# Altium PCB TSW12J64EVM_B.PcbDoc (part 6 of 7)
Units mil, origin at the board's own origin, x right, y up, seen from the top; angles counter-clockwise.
Board outline 8833 x 2680 mil, 10 copper layers (Top Layer L1, Gnd-Plane - L2, Signals - L3, Gnd-Plane - L4, Pwr Plane - L5, Signals - L6, Gnd-Plane - L7, Signals - L8, Gnd-Plane - L9, Bottom Layer - L10), stack 57.8 mil thick; 950 components, 533 nets, 2888 pads, 1732 vias.
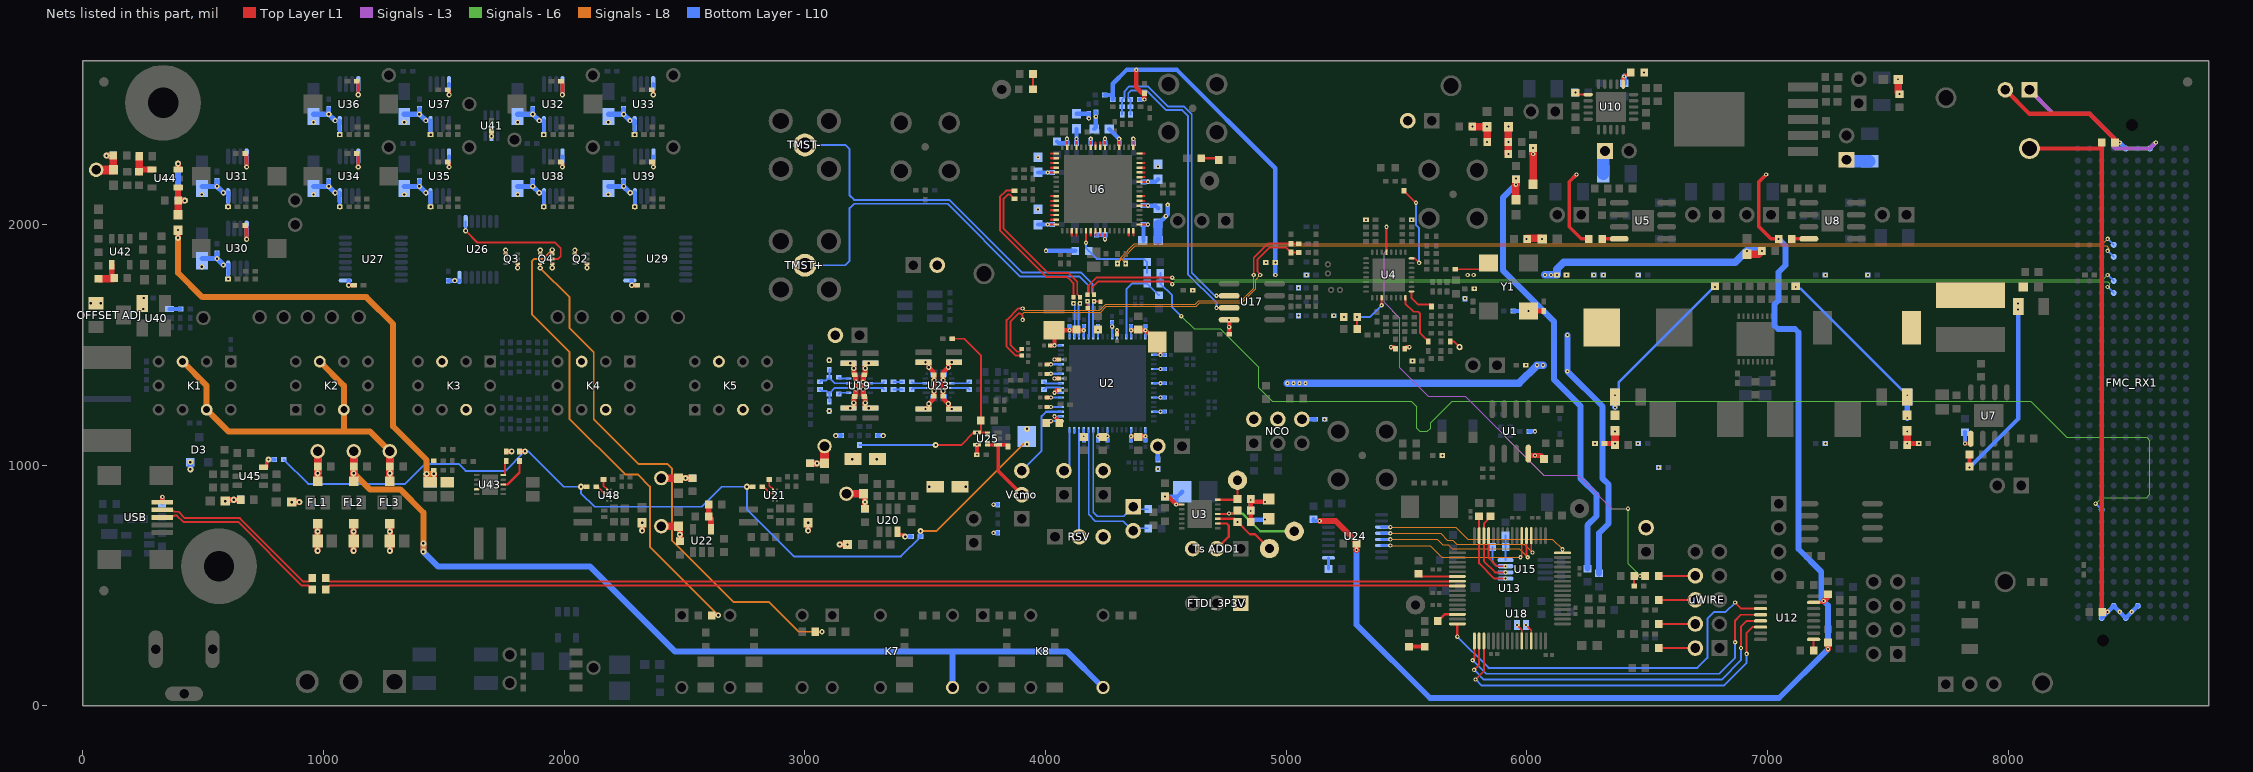
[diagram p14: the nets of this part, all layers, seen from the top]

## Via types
v1: diameter 18, hole 8, Top Layer L1 to Bottom Layer - L10, tented both sides, 1096 vias
v2: diameter 21.46, hole 10, Top Layer L1 to Bottom Layer - L10, tented both sides, 266 vias
v3: diameter 25, hole 10, Top Layer L1 to Bottom Layer - L10, tented both sides, 154 vias
v4: diameter 19.68, hole 7.87, Top Layer L1 to Bottom Layer - L10, 103 vias
v5: diameter 18, hole 8, Top Layer L1 to Bottom Layer - L10, tented bottom, 42 vias
v6: diameter 18, hole 8, Top Layer L1 to Bottom Layer - L10, tented top, 24 vias
v7: diameter 18, hole 8.01, Top Layer L1 to Bottom Layer - L10, tented both sides, 16 vias
v8: diameter 18, hole 8.01, Top Layer L1 to Bottom Layer - L10, tented bottom, 16 vias
v9: diameter 25.98, hole 12.99, Top Layer L1 to Bottom Layer - L10, tented top, 8 vias
v10: diameter 19.68, hole 7.87, Top Layer L1 to Bottom Layer - L10, tented top, 5 vias
v11: diameter 126, hole 106, Top Layer L1 to Bottom Layer - L10, tented top, 2 vias

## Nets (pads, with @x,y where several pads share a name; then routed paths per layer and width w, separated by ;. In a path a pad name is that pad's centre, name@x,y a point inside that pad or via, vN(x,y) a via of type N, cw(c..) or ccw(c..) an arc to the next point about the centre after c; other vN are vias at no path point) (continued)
NetQ4_3: Q4.3 R264.1 | length 2253.9
  Top Layer L1 w8: v2(1901,1818.65) Q4.3@1901,1836.39 ; R264.1@3044.12,307.56 v2(3071.6,307.56)
  Signals - L8 w8: v2(1901,1818.65) 2023,1696.65 2023,1569 2123,1469 2123,1191 2309,1005 2428,1005 2449,984 2449,686 2703,432 2850,432 2974.44,307.56 v2(3071.6,307.56)
NetQ4_5: Q4.5 U26.2 | length 537.6
  Top Layer L1 w8: v2(1590.82,1973.85) 1640.17,1924.5 1963.27,1924.5 1986,1901.77 1986,1866.77 1975.61,1856.39 Q4.5@1951,1856.39
  Bottom Layer - L10 w8: v2(1590.82,1973.85) U26.2@1590.82,2012.14
NetQ4_6: Q4.6 R263.1 | length 1971.8
  Top Layer L1 w8: Q4.6@1951,1876.39 v2(1951,1894.12) ; R263.1@2612.56,376 v2(2640.04,376)
  Signals - L8 w8: v2(1951,1894.12) 1913.27,1856.39 1876.39,1856.39 1866,1846 1866,1626 2023,1469 2023,1191 2253,961 2306,961 2356,911 2356,660.04 v2(2640.04,376)
NetR13_1: R13.1 U2.2 | length 62.9
  Top Layer L1 w18: v1(4037.26,1202.2) 4057.82,1181.65 R13.1@4057.82,1175
  Bottom Layer - L10 w9: v1(4037.26,1202.2) U2.2@4064.47,1202.2
NetR13_2: R13.2 U2.1 | length 64.9
  Top Layer L1 w18: R13.2@4002.7,1175 4010.22,1182.52 v1(4022.26,1182.52)
  Bottom Layer - L10 w9: v1(4022.26,1182.52) U2.1@4064.47,1182.52
NetR17_2: R17.2 TEMP.2 | length 63.6
  Bottom Layer - L10 w18: R17.2@4852.84,763.41 4862.84,773.41 v1(4912.28,773.41)
NetR26_2: R26.2 R133.1 Y1.1 | length 127.6
  Top Layer L1 w19.68: v1(6005.91,1640) R26.2@6070.47,1640
  Bottom Layer - L10 w18: R133.1@5942.92,1640 v1(6005.91,1640)
NetR38_2: R38.2 Y1.3 | length 149.8
  Top Layer L1 w8: R38.2@5701.69,1813.68 5814.24,1813.68 Y1.3@5840.56,1840
NetR39_2: R39.2 U5.8 | length 71
  Top Layer L1 w15: R39.2@6312.56,1940 U5.8@6383.57,1940
NetR45_2: R45.2 Status2.2 | length 63.7
  Top Layer L1 w9: Status2.2@3948.05,2561.29 R45.2@3948.06,2625
NetR47_1: R47.1 R142.2 R143.2 U6.6 | length 395.4
  Top Layer L1 w9: v1(4168.35,1923.69) U6.6@4168.35,1973.77
  Bottom Layer - L10 w8: v1(4168.35,1923.69) 4168.35,1901 R47.1@4179.35,1890 4212.35,1857 4408.44,1857 R142.2@4422.44,1843 R143.2@4422.44,1798.5
NetR52_1: R52.1 USB.2 | length 753.7
  Top Layer L1 w8: USB.2@330.71,813.93 371.71,813.93 379.46,806.18 397.98,806.18 424.17,780 652.63,780 916.94,515.69 938.24,515.69 R52.1@954.24,531.69
NetR52_2: R52.2 U13.7 | length 4709
  Top Layer L1 w8: R52.2@1009.36,531.69 1025.36,515.69 5676.63,515.69 5678.47,517.53 U13.7@5710.97,517.53
NetR53_1: R53.1 USB.3 | length 753.7
  Top Layer L1 w8: USB.3@330.71,782.44 371.71,782.44 379.46,790.18 391.36,790.18 417.54,764 646,764 910.31,499.69 938.24,499.69 R53.1@954.24,483.69
NetR53_2: R53.2 U13.8 | length 4709
  Top Layer L1 w8: R53.2@1009.36,483.69 1025.36,499.69 5676.63,499.69 5678.47,497.84 U13.8@5710.97,497.84
NetR56_2: R56.2 Status1.2 | length 72.9
  Top Layer L1 w9: Status1.2@4647.03,2274.95 R56.2@4719.94,2274.95
NetR65_2: R65.2 U12.9 | length 47
  Top Layer L1 w8: R65.2@7191.24,229 U12.9@7191.24,275.96
NetR66_1: R66.1 U13.14 | length 92.5
  Top Layer L1 w10: R66.1@5630.03,351.73 5658.03,379.73 U13.14@5710.97,379.73
NetR67_2: R67.2 U13.6 | length 164.9
  Top Layer L1 w10: R67.2@5550.47,547.96 5561.22,537.21 U13.6@5710.97,537.21
NetR70_2: R70.2 U7.1 | length 71.1
  Top Layer L1 w18: v1(7820.19,1090) U7.1@7844,1090
  Bottom Layer - L10 w18: v1(7820.19,1090) R70.2@7820.19,1137.29
NetR71_2: R71.2 U8.8 | length 71
  Top Layer L1 w15: R71.2@7100.56,1940 U8.8@7171.57,1940
NetR80_2: R80.2 R89.2 U10.11 | length 96
  Top Layer L1 w13.5: U10.11@6399.86,2582.49 6399.86,2609.67 v1(6404.36,2614.17) 6411.18,2621 6422.1,2621 R80.2@6432.1,2631
  Bottom Layer - L10 w24: R89.2@6404.36,2586.43 v1(6404.36,2614.17)
NetR85_1: R85.1 R88.2 U10.16 | length 55
  Top Layer L1 w8: v1(6202.68,2547.56) 6211.05,2539.18 U10.16@6254.19,2539.18
NetR97_2: R97.2 uWIRE.8 | length 152.4
  Top Layer L1 w8: R97.2@6547.56,540 uWIRE.8@6700,540
NetR98_2: R98.2 uWIRE.6 | length 152.4
  Top Layer L1 w8: R98.2@6547.56,440 uWIRE.6@6700,440
NetR99_1: R99.1 Tdiode.2 U2.64 | length 632.6
  Bottom Layer - L10 w6: U2.64@4178.65,1147.09 4178.65,796.36 4207.35,767.66 4323.62,767.66 Tdiode.2@4364.28,727 ; Tdiode.2@4364,727.28 4373.72,737 R99.1@4427.44,737
NetR100_1: R100.1 Tdiode.1 U2.63 | length 599.4
  Bottom Layer - L10 w6: U2.63@4198.33,1147.09 4198.33,804.52 4215.5,787.34 4324.62,787.34 Tdiode.1@4364.28,827 4374.28,817 R100.1@4427.44,817
NetR101_2: R101.2 uWIRE.4 | length 152.4
  Top Layer L1 w8: R101.2@6547.56,340 uWIRE.4@6700,340
NetR102_2: R102.2 uWIRE.2 | length 152.4
  Top Layer L1 w8: R102.2@6547.56,240 uWIRE.2@6700,240
NetR103_1: R103.1 USB.1 | length 49.6
  Top Layer L1 w19.5: USB.1@330.71,845.43 v1(330.71,867.27)
  Bottom Layer - L10 w16.5: R103.1@330.71,839.52 v1(330.71,867.27)
NetR105_1: R105.1 R108.2 U15.4 | length 102.1
  Bottom Layer - L10 w8: U15.4@5911.32,605.39 R108.2@5911.32,659 R105.1@5911.32,707.44
NetR106_1: R106.1 U13.62 U15.2 | length 307.2
  Top Layer L1 w8: R106.1@5848.2,787.44 5848.2,783.44 5821.2,756.44 U13.62@5821.2,706.5 5821.2,600.8 5867.8,554.2 v1(5911.32,554.2)
NetR107_1: R107.1 U13.63 U15.1 | length 332.3
  Top Layer L1 w8: R107.1@5800.2,787.44 5801.52,786.13 U13.63@5801.52,706.5 5801.52,591.48 5864.39,528.61 v1(5911.32,528.61)
NetR108_1: R108.1 U13.61 U15.3 | length 300.2
  Top Layer L1 w8: U13.61@5840.89,706.5 5840.89,614.11 5875.2,579.8 v1(5911.32,579.8)
  Bottom Layer - L10 w8: R108.1@5856.2,659 5856.2,598.8 5875.2,579.8 v1(5911.32,579.8)
NetR112_2: R112.2 USB_PWR.2 | length 64
  Top Layer L1 w16.5: R112.2@5510.91,245.68 USB_PWR.2@5574.91,245.68
NetR134_2: R134.2 R135.2 U2.30 | length 362.2
  Bottom Layer - L10 w8: U2.30@4336.13,1532.91 4336.13,1731.13 4359,1754 R134.2@4422.44,1754 R135.2@4470.64,1705.8
NetR145_1: R145.1 U4.25 | length 120.3
  Top Layer L1 w8: U4.25@5520.72,1721.1 5520.72,1693.7 5547.93,1666.5 R145.1@5602.33,1666.5
NetR149_2: R149.2 U4.24 | length 232.4
  Top Layer L1 w8: U4.24@5495.13,1695.51 5495.13,1671.16 5529.2,1637.09 5548.33,1637.09 5556.24,1629.19 5556.24,1547.68 R149.2@5590.24,1513.68
NetR150_2: R150.2 Vtune.1 | length 48.1
  Top Layer L1 w8: R150.2@5681.98,1513.68 5696.55,1513.68 Vtune.1@5720.24,1490
NetR151_2: R151.2 R152.1 U4.19 | length 203.4
  Top Layer L1 w8: R152.1@5294.56,1565 v1(5294.56,1615) ; v1@5396.71,1664.93 U4.19@5396.71,1695.51
  Bottom Layer - L10 w8: v1(5294.56,1615) 5346.78,1615 v1@5396.71,1664.93
  other v1: 5396.71,1664.07
NetR154_2: R154.2 U4.32 | length 365.4
  Top Layer L1 w8: R154.2@5489,2140 v1(5539,2090) ; U4.32@5520.72,1858.9 5533.27,1858.9 v1(5552.17,1840)
  Bottom Layer - L10 w8: v1(5539,2090) 5539,1998 5552.17,1984.83 v1(5552.17,1840)
NetR169_1: R169.1 R210.2 R241.1 U19.6 | length 169.1
  Bottom Layer - L10 w8: R169.1@3063.39,1345.84 3069.23,1351.68 3088.94,1351.68 R210.2@3101.86,1364.61 ; R241.1@3101.86,1396.32 R210.2@3101.86,1364.61 ; U19.6@3181.94,1340 3124.94,1340 3101.86,1363.08 R210.2@3101.86,1364.61
NetR170_2: R170.2 U20.3 | length 73.3
  Top Layer L1 w15: U20.3@3384.4,723.76 3384.4,710.48 3409.57,710.48 v3(3417.05,703)
  Bottom Layer - L10 w16: v3(3417.05,703) R170.2@3441.36,702.97
NetR173_2: R173.2 U21.B1 | length 56.7
  Top Layer L1 w8: R173.2@2822.67,910.02 2828.99,910.02 2856.11,882.9 U21.B1@2868.11,882.9
NetR175_1: R175.1 U21.A1 | length 45.9
  Top Layer L1 w8: R175.1@2852.3,938.02 2852.3,914.46 U21.A1@2868.11,898.65
NetR176_1: R176.1 R177.2 U22.4 | length 106.8
  Top Layer L1 w24: R177.2@2600.56,836 R176.1@2600.56,787 2610.4,777.16 U22.4@2610.4,733.24
NetR186_2: R186.2 U24.9 | length 46.4
  Bottom Layer - L10 w13: R186.2@5175.57,568 U24.9@5175.57,614.43
NetR203_2: R203.2 R209.2 R240.2 U19.5 | length 169.1
  Bottom Layer - L10 w8: R203.2@3063.39,1314.47 3069.23,1308.63 3088.94,1308.63 R209.2@3101.86,1295.71 ; R240.2@3101.86,1264 R209.2@3101.86,1295.71 ; U19.5@3181.94,1320.31 3124.94,1320.31 3101.86,1297.24 R209.2@3101.86,1295.71
NetR205_1: R205.1 U19.13 | length 58.6
  Bottom Layer - L10 w8: U19.13@3272.5,1320.31 3322.87,1320.31 R205.1@3328.71,1314.47
NetR205_2: R205.2 R207.1 | length 38.1
  Bottom Layer - L10 w8: R205.2@3368.08,1314.47 R207.1@3406.18,1314.47
NetR206_1: R206.1 U19.12 | length 58.6
  Bottom Layer - L10 w8: U19.12@3272.5,1340 3322.87,1340 R206.1@3328.71,1345.84
NetR206_2: R206.2 R208.2 | length 37.1
  Bottom Layer - L10 w8: R206.2@3368.08,1345.84 R208.2@3405.18,1345.84
NetR207_2: R207.2 U23.2 | length 58.6
  Bottom Layer - L10 w8: R207.2@3444.55,1314.47 3450.39,1320.32 U23.2@3500.76,1320.32
NetR208_1: R208.1 U23.3 | length 58.6
  Bottom Layer - L10 w8: R208.1@3444.55,1345.84 3450.39,1340 U23.3@3500.76,1340
NetR209_1: R209.1 U19.4 | length 42.8
  Bottom Layer - L10 w8: R209.1@3141.23,1295.71 3146.15,1300.63 U19.4@3181.94,1300.63
NetR210_1: R210.1 U19.7 | length 42.8
  Bottom Layer - L10 w8: R210.1@3141.23,1364.61 3146.15,1359.68 U19.7@3181.94,1359.68
NetR211_1: R211.1 U23.11 | length 75.1
  Bottom Layer - L10 w8: U23.11@3611,1320.32 3677.79,1320.32 R211.1@3683.63,1314.47
NetR212_1: R212.1 U23.10 | length 75.1
  Bottom Layer - L10 w8: U23.10@3611,1340 3677.79,1340 R212.1@3683.63,1345.84
NetR231_1: R231.1 R232.2 U42.4 | length 124.2
  Top Layer L1 w24: U42.4@120.6,1831.87 120.6,1787.95 R231.1@130.44,1778.11
  Top Layer L1 w31.5: R232.2@66,1773.4 125.73,1773.4 R231.1@130.44,1778.11
NetR233_1: R233.1 U40.1 | length 46.7
  Bottom Layer - L10 w15.75: U40.1@360.6,1648.4 R233.1@407.32,1648.4
NetR242_2: R242.2 U43.3 | length 136.9
  Top Layer L1 w9.45: U43.3@1747.12,919 1765,919 1815,969 R242.2@1815,1017.31
NetR243_2: R243.2 U43.5 | length 58.9
  Top Layer L1 w9.45: U43.5@1754.21,958.37 R243.2@1754.21,1017.32
NetR246_1: R246.1 R247.2 U44.4 | length 122.3
  Top Layer L1 w24: R246.1@234.11,2218.56 243.95,2228.4 U44.4@287.87,2228.4
  Top Layer L1 w31.5: R246.1@234.11,2218.56 R247.2@234.11,2283
NetR250_2: R250.2 U45.3 | length 73.3
  Top Layer L1 w15: U45.3@751.13,990.4 764.41,990.4 764.41,1015.57 v3(771.89,1023.05)
  Bottom Layer - L10 w16: v3@771.89,1023.03 R250.2@796.2,1023.03
NetR256_2: R256.2 U48.B1 | length 56.7
  Top Layer L1 w8: R256.2@2133.67,910.02 2139.99,910.02 2167.11,882.9 U48.B1@2179.11,882.9
NetR258_1: R258.1 U48.A1 | length 45.9
  Top Layer L1 w8: R258.1@2163.3,938.02 2163.3,914.46 U48.A1@2179.11,898.65
NetRSV_2: RSV.2 U2.66 | length 445.1
  Bottom Layer - L10 w9: RSV.2@4139.28,702 U2.66@4139.28,1147.09
"NetTs ADD1_2": "Ts ADD1.2" U3.9 | length 166.4
  Top Layer L1 w10: 4711.28,653 4761.28,703 4761.28,749 4752.89,757.39 U3.9@4715.08,757.39
NetU2_3: U2.3 Vcmo.3 | length 348.4
  Bottom Layer - L10 w9: Vcmo.3@3901.78,977 3984,1059.22 3984,1203 4002.89,1221.89 U2.3@4064.47,1221.89
NetU2_68: U2.68 Vbg.2 | length 179.7
  Bottom Layer - L10 w9: Vbg.2@4076.78,977 4099.91,1000.13 U2.68@4099.91,1147.09
NetU12_3: U12.3 U13.16 | length 1584.7
  Top Layer L1 w8: v1(6865.14,428.91) 6890.14,403.91 U12.3@6970.76,403.91
  Top Layer L1 w10: v1(5710.97,287) U13.16@5710.97,340.36
  Bottom Layer - L10 w8: v1(5710.97,287) 5840.97,157 6708,157 6750,199 6750,360.71 6779.29,390 6826.23,390 v1(6865.14,428.91)
NetU12_4: U12.4 U13.17 | length 1495
  Top Layer L1 w8: v1(5774.83,189.03) 5781.83,196.03 U13.17@5781.83,269.5 ; v1(6865.14,264) 6865.14,354.32 6889.14,378.32 U12.4@6970.76,378.32
  Bottom Layer - L10 w8: v1(5774.83,189.03) 5830.86,133 6799,133 6865.14,199.14 v1(6865.14,264)
NetU12_5: U12.5 U13.18 | length 1542.4
  Top Layer L1 w8: v1(5780.68,149.19) 5801.52,170.03 U13.18@5801.52,269.5 ; v1(6889.14,240) 6889.14,328.73 6913.14,352.73 U12.5@6994.76,352.73
  Bottom Layer - L10 w8: v1(5780.68,149.19) 5820.86,109 6808.94,109 6889.14,189.2 v1(6889.14,240)
NetU12_6: U12.6 U13.19 | length 1541.7
  Top Layer L1 w8: v1(5786.52,109.34) 5821.2,144.03 U13.19@5821.2,269.5 ; v1(6913.14,216) 6913.14,303.14 6937.14,327.14 U12.6@6970.76,327.14
  Bottom Layer - L10 w8: v1(5786.52,109.34) 5810.86,85 6818.88,85 6913.14,179.26 v1(6913.14,216)
NetU13_27: U13.27 U18.2 | length 74.8
  Top Layer L1 w8: v1(5958.68,335.96) 5978.68,315.96 U13.27@5978.68,269.5
NetU13_29: U13.29 U18.1 | length 75.6
  Top Layer L1 w8: v1(5996.07,335.96) 6018.05,313.98 U13.29@6018.05,269.5
NetU13_48: U13.48 U24.3 | length 804.4
  Top Layer L1 w11.81: U13.48@6147.98,635.64 v1(6147.98,649.69)
  Signals - L8 w4: v1(5432.61,742.39) 5703.61,742.39 5753.96,692.04 6105.63,692.03 v1(6147.98,649.69)
  Bottom Layer - L10 w13: U24.3@5396.05,742.39 v1(5432.61,742.39)
NetU13_52: U13.52 U24.4 | length 731.6
  Top Layer L1 w8: U13.52@6018.05,706.5 6018.05,642.04 v1(6023.06,637.04)
  Signals - L8 w4: v1(5432.61,716.8) 5641.21,716.79 5670,688 5692,688 5707.96,672.04 5988.06,672.03 v1(6023.06,637.04)
  Bottom Layer - L10 w13: U24.4@5396.05,716.8 v1(5432.61,716.8)
NetU13_53: U13.53 U24.5 | length 729.6
  Top Layer L1 w8: U13.53@5998.37,706.5 5998.37,622.04 v1(6003.37,617.04)
  Signals - L8 w4: v1(5432.61,691.2) 5627.8,691.2 5651,668 5673,668 5688.97,652.03 5968.37,652.03 v1(6003.37,617.04)
  Bottom Layer - L10 w13: U24.5@5396.05,691.2 v1(5432.61,691.2)
NetU13_54: U13.54 U24.6 | length 689.3
  Top Layer L1 w8: v1(5973.68,617.03) 5978.68,622.04 U13.54@5978.68,706.5
  Signals - L8 w4: v1(5432.61,665.61) 5598.39,665.61 5646.96,617.04 v1(5973.68,617.03)
  Bottom Layer - L10 w13: U24.6@5396.05,665.61 v1(5432.61,665.61)
PG_C2M_RX: FMC_RX1.D1 PG_RX1.1 | length 692.9
  Signals - L3 w18: PG_RX1.1@8088,2559 8188,2459 8338,2459 8438,2359 8438,2323 8446,2315 8588,2315 v5(8613,2340)
  Bottom Layer - L10 w18: FMC_RX1.D1@8588,2315 v5(8613,2340)
PG_M2C_RX: FMC_RX1.F1 PG_RX1.2 RR6.1 | length 609.2
  Top Layer L1 w18: PG_RX1.2@7988,2559 8088,2459 8338,2459 8443.12,2353.88 RR6.1@8443.12,2340 v1(8463,2340)
  Bottom Layer - L10 w18: v1(8463,2340) FMC_RX1.F1@8488,2315
SYNC_N: FMC_RX1.G13 R20.2 | length 4335.8
  Top Layer L1 w8: R20.2@4201,1707.98 4192,1716.98 4192,1737 4217.5,1762.5 4515.55,1762.5 v1(4526.55,1751.5)
  Signals - L6 w4: v1(4526.55,1751.5) 4536.05,1761 8413,1761 8421,1753 8421,1748 v5(8413,1740)
  Bottom Layer - L10 w8: v5(8413,1740) FMC_RX1.G13@8438,1715
SYNC_P: FMC_RX1.G12 R19.2 | length 4335.9
  Top Layer L1 w8: R19.2@4174,1707.98 4176,1709.98 4176,1743.63 4210.87,1778.5 v1(4526.55,1778.5)
  Signals - L6 w4: v1(4526.55,1778.5) 4536.05,1769 8392,1769 v5(8413,1790)
  Bottom Layer - L10 w8: v5(8413,1790) FMC_RX1.G12@8438,1765
SYNC_SE: FMC_RX1.H31 R134.1 R143.1 | length 5174
  Signals - L6 w4: v1(4564,1619) 4617,1566 4726,1566 4885,1407 4885,1321 4941,1265 5521,1265 ; 5520.5,1264.5 5542,1243 5542,1153 5555,1140 5587,1140 5600,1153 5600,1176 5689,1265 8093,1265 8243,1115 8575,1115 8588,1102 8588,878 8575,865 8388,865 v5(8363,840)
  Bottom Layer - L10 w8: R143.1@4477.56,1798.5 R134.1@4477.56,1754 4526.36,1705.2 4526.36,1656.64 v1(4564,1619) ; v5(8363,840) FMC_RX1.H31@8388,815
SYNC~/TMST_N: R20.1 R21.1 R23.1 U2.23 | length 178.8
  Top Layer L1 w8: R20.1@4201.99,1681.01 4204.01,1678.99 R23.1@4229,1678.99
  Bottom Layer - L10 w8: U2.23@4198.33,1532.91 4196.49,1534.76 4196.49,1675.32 v1(4201.99,1680.82)
SYNC~/TMST_P: R18.1 R19.1 R22.1 U2.22 | length 179
  Top Layer L1 w8: R22.1@4175.01,1653 R19.1@4174.99,1681.01
  Bottom Layer - L10 w8: v1(4174.99,1680.82) 4180.49,1675.31 4180.49,1534.76 U2.22@4178.65,1532.91
SYSREFRX_N: FMC_RX1.G10 R61.2 | length 4198.7
  Signals - L8 w4: v1(4332.99,1837.32) 4319.99,1850.32 4319.99,1858.13 4372.86,1911 8408,1911 8418,1901 8418,1895 v5(8413,1890)
  Bottom Layer - L10 w8: v5(8413,1890) FMC_RX1.G10@8438,1865
SYSREFRX_P: FMC_RX1.G9 R62.2 | length 4198.4
  Signals - L8 w4: v1(4298.99,1837.32) 4311.99,1850.32 4311.99,1861.45 4369.54,1919 8392,1919 v5(8413,1940)
  Bottom Layer - L10 w8: v5(8413,1940) FMC_RX1.G9@8438,1915
SYSREFTX_N: C37.2 R43.2 | length 640.2
  Top Layer L1 w8: R43.2@3871.1,2106 3853.1,2124 3843.04,2124 3826.23,2107.19 3826.23,1982.37 4011.23,1797.37 4097.25,1797.37 4131.96,1762.66 4131.96,1709.04 C37.2@4136,1705
SYSREFTX_P: C35.2 R44.2 | length 664.5
  Top Layer L1 w8: R44.2@3871.1,2140 3836.41,2140 3810.23,2113.81 3810.23,1975.74 3847,1938.97 4004.6,1781.37 4090.62,1781.37 4101.93,1770.05 4115.96,1756.03 C35.2@4115.96,1698.02
SYSRF_N: C37.1 C91.1 U2.20 | length 141.9
  Bottom Layer - L10 w8: U2.20@4139.28,1532.91 4137.43,1534.76 4137.43,1666.32 v1(4142.93,1671.82)
SYSRF_P: C35.1 C90.1 U2.19 | length 141.9
  Bottom Layer - L10 w8: C90.1@4115.93,1671.82 4121.43,1666.31 4121.43,1534.76 U2.19@4119.59,1532.91
  other v1: 4115.93,1672.01
TCRIT1: R16.1 R17.1 TCRIT1.1 U3.10 | length 266.6
  Top Layer L1 w9: U3.10@4715.08,777.07 4785.06,777.07 v1(4797.72,764.41) 4849.13,713 4870.28,713 TCRIT1.1@4930.28,653
TCRIT2: R15.1 TCRIT2.1 U3.11 | length 390.5
  Top Layer L1 w9: U3.11@4715.08,796.76 4760.28,796.76 v1(4762.28,798.76) 4785.06,798.76 R15.1@4797.72,811.41
  Signals - L6 w9: v1(4762.28,798.76) 4818.49,798.76 4892.25,725 TCRIT2.1@5033.5,725
TCRIT3: R14.1 TCRIT3.1 U3.14 | length 163.8
  Top Layer L1 w9: U3.14@4715.08,855.81 4797.72,855.81 TCRIT3.1@4797.72,937
TMST_N: R21.2 TMST-.1 | length 1595.2
  Bottom Layer - L10 w8: TMST-.1@3000,2330.16 3168,2330.16 3186.2,2311.95 3186.2,2120.03 3204.58,2101.66 3600.31,2101.66 3902.6,1799.37 4148.26,1799.37 4195.5,1752.13 4195.5,1713.48 R21.2@4201.99,1706.99
TMST_P: R18.2 TMST+.1 | length 1594.8
  Bottom Layer - L10 w8: TMST+.1@3000,1830.16 3168,1830.16 3186.2,1848.36 3186.2,2067.28 3204.58,2085.66 3593.68,2085.66 3895.98,1783.37 4141.63,1783.37 4179.5,1745.5 4179.5,1711.5 R18.2@4174.99,1706.99
TRF3765_STROBE: R97.1 R113.1 R116.2 R119.1 U4.5 | length 2323.1
  Top Layer L1 w8: U4.5@5416.39,1884.49 v1(5416.39,1990) ; R116.2@6445.56,498 R113.1@6445.56,540 R97.1@6492.44,540
  Signals - L3 w4: v1(5416.39,1990) 5416.39,1890 5406.55,1880.16 5406.55,1676.45 5472,1611 5472,1405 5591,1286 5743,1286 6071,958 6213,958 6352,819 v1(6420,819)
  Signals - L6 w4: v1(6420,819) 6420,590.56 v1(6470.56,540)
  Bottom Layer - L10 w8: v1(6470.56,540) R119.1@6492.44,540
TRF_OUTA_N: C112.2 R157.1 R159.2 U17.6 | length 1288.2
  Top Layer L1 w8: v1(4710.54,1703.5) U17.6@4762.84,1703.5
  Bottom Layer - L10 w8: C112.2@4318.67,2456.69 R157.1@4318.67,2519 4327.67,2528 4327.67,2551.96 4348.71,2573 4425.63,2573 4508.25,2490.38 4574.13,2490.38 4607.5,2457 4607.5,1799.46 4703.46,1703.5 v1(4710.54,1703.5)
TRF_OUTA_P: C113.2 R156.1 R158.2 U17.7 | length 1287.7
  Top Layer L1 w8: v1(4710.54,1653.5) U17.7@4762.84,1653.5
  Bottom Layer - L10 w8: C113.2@4352.67,2456.69 R156.1@4352.67,2519 4343.67,2528 4343.67,2545.33 4355.34,2557 4419,2557 4501.62,2474.38 4567.5,2474.38 4591.5,2450.38 4591.5,1792.83 4710.54,1673.8 v1(4710.54,1653.5)
TRF_OUTB_N: C33.2 C83.2 R36.2 | length 1614.8
  Top Layer L1 w8: C33.2@3901.59,1481.45 3891.14,1471 3882.04,1471 3854,1499.04 3854,1595.37 3888.63,1630 3895.95,1630 3905,1620.95 v1(3905,1603.65) ; v1@4892,1792.7 4881,1803.7 4881,1854.5 4930.31,1903.81 4999.42,1903.81 R36.2@5020.05,1883.18 C83.2@5052.36,1883.18
  Signals - L8 w4: v1(3905,1603.65) 3905,1628.65 3912,1635.65 4228.58,1635.65 4252.94,1660 4626.31,1660 4640.81,1674.5 4815.81,1674.5 4873,1731.69 4873,1771 v1(4892,1790)
TRF_OUTB_P: C32.2 C75.2 R29.2 | length 1614.6
  Top Layer L1 w8: C32.2@3901.59,1454.45 3901.04,1455 3875.41,1455 3838,1492.41 3838,1602 3886.65,1650.65 v1(3905,1650.65) ; v1(4865,1790) 4865,1861.13 4923.69,1919.81 R29.2@5020.05,1919.81 C75.2@5052.36,1919.81
  Signals - L8 w4: v1(3905,1650.65) 3912,1643.65 4225.27,1643.65 4249.62,1668 4623,1668 4637.5,1682.5 4812.5,1682.5 4865,1735 v1(4865,1790)
U2-67: U2.67 | length 14.1
  Bottom Layer - L10 w9: 4119.59,1133 U2.67@4119.59,1147.09
U6-3: U6.3 | length 20.5
  Top Layer L1 w9: 4109.29,1953.27 U6.3@4109.29,1973.77
U6-4: U6.4 | length 20.5
  Top Layer L1 w9: 4128.98,1953.27 U6.4@4128.98,1973.77
U6-7: U6.7 | length 20.5
  Top Layer L1 w9: 4188.03,1953.27 U6.7@4188.03,1973.77
U6-8: U6.8 | length 20.5
  Top Layer L1 w9: 4207.72,1953.27 U6.8@4207.72,1973.77
U6-9: U6.9 | length 20.5
  Top Layer L1 w9: 4227.4,1953.27 U6.9@4227.4,1973.77
U6-15: U6.15 | length 20.5
  Top Layer L1 w9: 4345.51,1953.27 U6.15@4345.51,1973.77
U6-16: U6.16 | length 20.5
  Top Layer L1 w9: 4365.2,1953.27 U6.16@4365.2,1973.77
U6-22: U6.22 | length 20.5
  Top Layer L1 w9: U6.22@4390.79,2097.79 4411.29,2097.79
U6-23: U6.23 | length 20.5
  Top Layer L1 w9: U6.23@4390.79,2117.47 4411.29,2117.47
U6-27: U6.27 | length 20.5
  Top Layer L1 w9: U6.27@4390.79,2196.21 4411.29,2196.21
U6-28: U6.28 | length 20.5
  Top Layer L1 w9: U6.28@4390.79,2215.9 4411.29,2215.9
U6-29: U6.29 | length 20.5
  Top Layer L1 w9: U6.29@4390.79,2235.58 4411.29,2235.58
U6-30: U6.30 | length 20.5
  Top Layer L1 w9: U6.30@4390.79,2255.27 4411.29,2255.27
U6-32: U6.32 | length 20.5
  Top Layer L1 w9: U6.32@4390.79,2294.64 4411.29,2294.64
U6-40: U6.40 | length 20.5
  Top Layer L1 w9: U6.40@4227.4,2320.23 4227.4,2340.73
U6-41: U6.41 | length 20.5
  Top Layer L1 w9: U6.41@4207.72,2320.23 4207.72,2340.73
U6-49: U6.49 | length 20.5
  Top Layer L1 w9: 4023.83,2294.64 U6.49@4044.33,2294.64
U6-50: U6.50 | length 20.5
  Top Layer L1 w9: 4023.83,2274.95 U6.50@4044.33,2274.95
U6-51: U6.51 | length 20.5
  Top Layer L1 w9: 4023.83,2255.27 U6.51@4044.33,2255.27
U6-52: U6.52 | length 20.5
  Top Layer L1 w9: 4023.83,2235.58 U6.52@4044.33,2235.58
U6-58: U6.58 | length 20.5
  Top Layer L1 w9: 4023.83,2117.47 U6.58@4044.33,2117.47
U6-59: U6.59 | length 20.5
  Top Layer L1 w9: 4023.83,2097.79 U6.59@4044.33,2097.79
U6-60: U6.60 | length 20.5
  Top Layer L1 w9: 4023.83,2078.1 U6.60@4044.33,2078.1
U6-61: U6.61 | length 20.5
  Top Layer L1 w9: 4023.83,2058.42 U6.61@4044.33,2058.42
U6-62: U6.62 | length 20.5
  Top Layer L1 w9: 4023.83,2038.73 U6.62@4044.33,2038.73
U6-63: U6.63 | length 20.5
  Top Layer L1 w9: 4023.83,2019.05 U6.63@4044.33,2019.05
VADJ_RX: FMC_RX1.E39 FMC_RX1.F40 FMC_RX1.G39 FMC_RX1.H40 RR6.2 RR7.1 VADJ_RX.1 | length 2487.1
  Top Layer L1 w18: VADJ_RX.1@8088,2315 8388,2315 ; RR6.2@8388,2340 8388,2315 ; v1(8413,390) 8388,390 8388,2315
  Bottom Layer - L10 w18: FMC_RX1.H40@8388,365 v1(8413,390) FMC_RX1.G39@8438,415 v5(8463,390) FMC_RX1.F40@8488,365 v5(8513,390) FMC_RX1.E39@8538,415
VCC2: C103.1 L2.2 U6.17 | length 120.8
  Top Layer L1 w9: U6.17@4390.79,1999.36 v1(4425.87,1999.36)
  Bottom Layer - L10 w18: L2.2@4407,1932.5 C103.1@4407,1999.36 v1(4425.87,1999.36)
VCC3: C106.1 L4.2 U6.21 | length 100.4
  Top Layer L1 w9: U6.21@4390.79,2078.1 v1(4425.87,2078.1)
  Bottom Layer - L10 w18: C106.1@4407,2078.1 v1(4425.87,2078.1) 4457.23,2078.1 L4.2@4467.92,2067.42
VCC4: C111.1 L19.2 U6.26 | length 100.4
  Top Layer L1 w9: U6.26@4390.79,2176.53 v1(4425.87,2176.53)
  Bottom Layer - L10 w18: C111.1@4407,2176.53 v1(4425.87,2176.53) 4457.23,2176.53 L19.2@4467.92,2187.21
VCC6: C105.1 L3.2 U6.36 | length 112.2
  Top Layer L1 w9: U6.36@4306.14,2320.23 v1(4306.14,2355.31)
  Bottom Layer - L10 w18: L3.2@4264.95,2396.5 v1(4306.14,2355.31) C105.1@4306.14,2336.45
VCC9: C110.1 L5.2 U6.45 | length 95.1
  Top Layer L1 w9: U6.45@4128.98,2320.23 v1(4128.98,2355.31)
  Bottom Layer - L10 w18: C110.1@4128.98,2336.45 v1(4128.98,2355.31) L5.2@4128.98,2396.5
VCC11: C120.1 L21.2 U6.53 | length 93.7
  Top Layer L1 w9: v1(4009.24,2215.9) U6.53@4044.33,2215.9
  Bottom Layer - L10 w18: L21.2@3969.5,2215.9 v1(4009.24,2215.9) C120.1@4028.11,2215.9
VCC12: C121.1 L22.2 U6.64 | length 93.7
  Top Layer L1 w9: v1(4009.24,1999.36) U6.64@4044.33,1999.36
  Bottom Layer - L10 w18: L22.2@3969.5,1999.36 v1(4009.24,1999.36) C121.1@4028.11,1999.36
VCMO: C310.2 R239.2 U25.1 Vcmo.2 | length 338
  Top Layer L1 w15.75: R239.2@3759.12,1089.31 3764.02,1084.41 U25.1@3803.41,1084.41 ; C310.2@3844.12,1077.52 3837.23,1084.41 U25.1@3803.41,1084.41 ; Vcmo.2@3901.78,877 3803.41,975.37 U25.1@3803.41,1084.41
VCMO_LMH5401: C99.1 R178.1 R181.1 R239.1 U25.4 | length 1024.6
  Top Layer L1 w8: v3(3543.69,1083.31) 3650.43,1083.31 3702.71,1135.59 v1(3714.83,1135.59) 3752.21,1135.59 R239.1@3759.12,1128.68 ; R181.1@3611.98,1525 3662,1525 3731.56,1455.44 C99.1@3731.56,1186 3731.56,1135.59
  Bottom Layer - L10 w8: R178.1@3227.22,1083.31 v3(3543.69,1083.31)
VIN_N: R180.2 U2.9 | length 74.4
  Bottom Layer - L10 w8: R180.2@3994,1345.84 4001.69,1338.16 4062.63,1338.16 U2.9@4064.47,1340
VIN_P: R179.2 U2.8 | length 74.4
  Bottom Layer - L10 w8: R179.2@3994,1314.47 4001.69,1322.16 4062.63,1322.16 U2.8@4064.47,1320.31
VIO_1P2VA: C39.1 C40.1 C41.2 C42.2 C43.2 C44.2 C45.2 C46.2 C47.2 C48.1 C177.1 C188.1 L15.2 U2.6 U2.11 U2.14 U2.17 U2.18 U2.21 U2.65 VA12.2 | length 654.1
  Top Layer L1 w16: C41.2@4004.64,1280.94 v1(4022.26,1280.94) ; C42.2@4004.64,1379.37 v1(4022.26,1379.37) ; C44.2@4019.64,1497.48 v1(4037.26,1497.48) ; v1(4037.26,1438.43) C43.2@4054.88,1438.43
  Top Layer L1 w18: v1(4037.26,1497.48) 4037.26,1560.13 v1(4099.91,1560.13) v1(4158.96,1560.13)
  Top Layer L1 w31.5: v1(5773.56,2406.01) v1(5835,2406.01) v1(5835,2341.5)
  Bottom Layer - L10 w9: v1(4022.26,1280.94) U2.6@4064.47,1280.94 ; v1(4022.26,1379.37) U2.11@4064.47,1379.37 ; v1(4037.26,1438.43) U2.14@4064.47,1438.43 ; v1(4037.26,1497.48) U2.17@4064.47,1497.48 ; U2.18@4099.91,1532.91 v1(4099.91,1560.13) ; v1(4158.96,1119.87) U2.65@4158.96,1147.09 ; U2.21@4158.96,1532.91 v1(4158.96,1560.13)
  Bottom Layer - L10 w16: v1(4099.91,1560.13) C45.2@4099.91,1577.75 ; C47.2@4158.96,1102.25 v1(4158.96,1119.87) ; v1(4158.96,1560.13) C46.2@4158.96,1577.75
VIO_1P2VD: C60.1 C61.1 C62.2 C63.2 C64.2 C65.2 C66.2 C67.2 C68.2 C69.2 C70.2 C71.2 C72.1 C95.2 C96.2 C189.1 C197.1 L16.2 NCO.2 NCO.4 NCO.6 RSV.3 U2.28 U2.31 U2.34 U2.37 U2.40 U2.43 U2.46 U2.49 U2.52 U2.55 VD12.2 | length 917.5
  Top Layer L1 w16: C71.2@4296.76,1542.5 v1(4296.76,1560.13)
  Top Layer L1 w18: v1(4355.81,1119.87) v1(4414.87,1119.87) ; v1(4355.81,1560.13) v1(4414.87,1560.13) 4462.25,1512.74 4462.25,1511.4 4477.51,1496.14 v1(4477.51,1458.11)
  Top Layer L1 w31.5: v1(5923,2292.5) v1(5923,2406.01)
  Bottom Layer - L10 w9: U2.28@4296.76,1532.91 v1(4296.76,1560.13) ; v1(4355.81,1119.87) U2.55@4355.81,1147.09 ; U2.31@4355.81,1532.91 v1(4355.81,1560.13) ; v1(4414.87,1119.87) U2.52@4414.87,1147.09 ; U2.34@4414.87,1532.91 v1(4414.87,1560.13) ; U2.49@4450.3,1221.89 v1(4477.51,1221.89) ; U2.46@4450.3,1280.94 v1(4477.51,1280.94) ; U2.43@4450.3,1340 v1(4477.51,1340) ; U2.40@4450.3,1399.06 v1(4477.51,1399.06) ; U2.37@4450.3,1458.11 v1(4477.51,1458.11)
  Bottom Layer - L10 w16: C62.2@4355.81,1102.25 v1(4355.81,1119.87) ; v1(4355.81,1560.13) C70.2@4355.81,1577.75 ; C63.2@4414.87,1102.25 v1(4414.87,1119.87) ; v1(4414.87,1560.13) C69.2@4414.87,1577.75 ; v1(4477.51,1221.89) C64.2@4495.13,1221.89 ; v1(4477.51,1280.94) C65.2@4495.13,1280.95 ; v1(4477.51,1340) C66.2@4495.13,1340 ; v1(4477.51,1399.06) C67.2@4495.13,1399.05 ; v1(4477.51,1458.11) C68.2@4495.13,1458.11
  Bottom Layer - L10 w18: C96.2@4467,1023.19 VD12.2@4467,1078 ; NCO.6@5065.5,1190 C95.2@5120.31,1190
  other v1: 5923,2341.5
VIO_1P4: 1V2ADC_INT.1 C176.1 C190.1 C219.1 C221.1 C224.1 C225.1 L14.2 R83.1 | length 253.7
  Top Layer L1 w19.5: C219.1@6322.53,1090 v1(6365.85,1090)
  Top Layer L1 w31.5: v1(6365.85,1090) L14.2@6365.85,1143.5
  Bottom Layer - L10 w24: C190.1@6365.85,1084 v1@6365.85,1143.5
  Bottom Layer - L10 w51: R83.1@6317.18,2210.56 6317.18,2297.91 1V2ADC_INT.1@6324.27,2305
  other v1: 6462.31,1090 6365.85,1140 6317.68,1790 6462.31,1790
VIO_1P4V: C175.1 C182.1 C183.1 L12.2 L14.1 R82.2 | length 675.5
  Bottom Layer - L10 w10: C183.1@6365.85,1283 6382,1299.15 6382,1344.56 R82.2@6781,1743.56
  Bottom Layer - L10 w24: v1@6365.85,1240 C183.1@6365.85,1283
  other v1: 6365.85,1240 6365.85,1290 6781,1740
VIO_1P9V: C49.1 C50.1 C51.2 C52.2 C53.2 C54.2 C55.2 C56.2 C57.2 C58.2 C59.1 C98.1 C130.1 C191.1 C202.1 L18.2 R39.1 R71.1 R80.1 R123.2 R170.1 R173.1 R187.2 R242.1 R250.1 R256.1 U2.4 U2.7 U2.10 U2.13 U2.24 U2.27 U2.60 U2.62 U12.15 U24.15 VA19.2 | length 9690.4
  Top Layer L1 w13: U12.15@7191.24,429.5 7227.5,429.5 v1(7233,435)
  Top Layer L1 w15: v1(6206,2207) 6176,2177 6176,1990 6226,1940 R39.1@6257.44,1940 ; v1(6994,2207) 6964,2177 6964,1990 7014,1940 v1(7045.44,1940)
  Top Layer L1 w16: v3(2069.99,910.02) R256.1@2094.3,910.02 ; v3(2758.99,910.02) R173.1@2783.3,910.02 ; C51.2@4004.64,1241.57 v1(4022.26,1241.57) ; C54.2@4004.64,1418.74 v1(4022.26,1418.74) ; v1(4037.26,1359.68) C53.2@4054.88,1359.68
  Top Layer L1 w18: v1(4037.26,1300.63) 4047.58,1310.95 C52.2@4057.57,1310.95
  Top Layer L1 w19.68: R242.1@1815,1056.68 v3(1837.34,1056.68)
  Top Layer L1 w24: v1(5139.02,767.98) 5205.76,767.98 5292,681.73 R187.2@5292,673.35 v1(5292,647.61) ; v1(7233,435) 7251,453 C130.1@7251,462.75 ; v1(7251,235.22) R123.2@7251,262.97
  Top Layer L1 w31.5: v1(7542.5,2602.93) 7542.5,2546.49 v1(7547.5,2541.49)
  Signals - L8 w8: v3(3480.76,725.31) 3545.31,725.31 3907.08,1087.08 v3(3923,1087.08)
  Bottom Layer - L10 w8: R250.1@835.57,1023.03 936.6,922 1340,922 1423,1005 1562,1005 1591,976 1756.66,976 v3(1837.34,1056.68) 1851.32,1056.68 1997.98,910.02 v3(2069.99,910.02) 2069.99,884.01 2127,827 2572,827 2655.02,910.02 v3(2758.99,910.02) 2758.99,817.01 2955,621 3398.76,621 R170.1@3480.73,702.97
  Bottom Layer - L10 w9: v1(4022.26,1241.57) U2.4@4064.47,1241.57 ; v1(4022.26,1418.74) U2.13@4064.47,1418.74 ; v1(4037.26,1300.63) U2.7@4064.47,1300.63 ; v1(4037.26,1359.68) U2.10@4064.47,1359.68 ; v1(4218.02,1119.87) U2.62@4218.02,1147.09 ; U2.24@4218.02,1532.91 v1(4218.02,1560.13) ; v1(4257.39,1119.87) U2.60@4257.39,1147.09 ; U2.27@4277.07,1532.91 v1(4277.07,1575.13)
  Bottom Layer - L10 w13: v1(5139.02,767.98) U24.15@5175.57,767.98
  Bottom Layer - L10 w16: R170.1@3480.73,702.97 v3@3480.73,725.31 ; C58.2@4218.02,1102.25 v1(4218.02,1119.87) ; v1(4218.02,1560.13) C55.2@4218.02,1577.75 ; C57.2@4257.39,1102.25 v1(4257.39,1119.87) ; v1(4277.07,1575.13) C56.2@4277.07,1592.75
  Bottom Layer - L10 w18: C98.1@5113.28,774.72 5113.28,767.98 v1(5139.02,767.98)
  Bottom Layer - L10 w24: v1(5292,647.61) 5292,337 5597,32 7047.78,32 v1(7251,235.22) 7251,417 v1(7233,435) 7223,445 7223,557 7128.61,651.39 7128.61,1550.36 7113.97,1565 7043.25,1565 7028.61,1579.64 7028.61,1667.58 7045,1683.97 7045,1801 7074,1830 7074,1911.44 v1(7045.44,1940)
  other v1: 6487.22,2631
  other v3: 3923,1150.66
VIO_2P25: 1V9INT.1 C199.1 C203.1 C222.1 C223.1 C226.1 C227.1 L20.2 R95.1 | length 258.5
  Top Layer L1 w19.5: v1(7580.15,1090) v1(7628.32,1090)
  Top Layer L1 w31.5: v1(7580.15,1090) L20.2@7580.15,1143.5
  Bottom Layer - L10 w24: C203.1@7580.15,1084 v1@7580.15,1143.5
  Bottom Layer - L10 w51: 1V9INT.1@7328,2269.07 7335.09,2261.98 R95.1@7422.44,2261.98
  other v1: 7239.69,1090 7580.15,1140 7239.69,1790 7416.32,1790
VIO_2P25V: C174.2 C180.1 C181.1 L11.1 L20.1 R81.1 | length 745.3
  Bottom Layer - L10 w10: R81.1@7117,1743.56 7127.56,1733 7136,1733 7564,1305 7564,1299.15 C181.1@7580.15,1283
  Bottom Layer - L10 w24: v1@7580.15,1195 C181.1@7580.15,1283
  other v1: 7580.15,1195 7580.15,1290 7117,1740
VIO_3: C410.1 C411.1 D3.2 L54.2 | length 168.9
  Top Layer L1 w24: v3(593.02,850.01) 599.01,856 v3(627.51,856) C411.1@655.76,856
  Bottom Layer - L10 w24: C410.1@655.76,856 v3(627.51,856) v3@599.01,856 ; v3@599.01,856 v3(593.02,850.01) v3@599.01,856
  Bottom Layer - L10 w25: v3(447.18,982.5) v3(447.18,1012.5)
VIO_3P3V: "Ts ADD1.3" C24.1 C25.1 C27.1 C95.1 C96.1 C115.1 C125.1 C153.1 C163.1 C215.1 C216.1 C217.1 C218.1 C219.2 C220.1 C224.2 FTDI_3P3V.1 J3.2 L9.2 R1.2 R14.2 R15.2 R16.2 R31.2 R32.2 TEMP.1 U1.8 U3.2 | length 651.2
  Top Layer L1 w9: v1(4543.28,836.13) U3.2@4565.47,836.13
  Top Layer L1 w18: v1(4497.28,869.44) 4509.96,869.44 v1(4543.28,836.13) ; R16.2@4852.84,763.41 v1(4852.84,809.41) 4852.84,847.47 v1(4912.28,847.47)
  Top Layer L1 w19.5: U1.8@6006,1040 6056.93,1040 C125.1@6070.93,1026
  Top Layer L1 w30: C153.1@5999,1942.56 6060.45,1942.56 v1(6063.01,1940)
  Bottom Layer - L10 w18: v1(4497.28,869.44) 4548.17,869.44 C27.1@4568.14,889.42 ; v1(4543.28,836.13) C27.1@4543.3,869.44 ; v1(4852.84,809.41) v1(4852.84,855.81) ; v1(5999,1940) v1(6063.01,1940) ; R1.2@6009.69,1140 v1(6033.5,1140)
  Bottom Layer - L10 w19.5: v1(6033.5,1040) 6056.93,1040 C115.1@6070.93,1026
  other v1: 4467,983.82 6547.31,990 5648.69,1040 6283.16,1090 5159.69,1190 4611.69,1726 6164.24,1790 6278.31,1790 4915.31,1842
VIO_3P3V_LMK_CLK: C116.1 C171.1 L2.1 L4.1 L13.2 L19.1 L21.1 L22.1 R47.2 R131.1 | length 2191.3
  Top Layer L1 w31.5: L13.2@5954,2102.99 C116.1@5954,2187.44
  Bottom Layer - L10 w18: v1(4002,1890) R47.2@4124.23,1890 ; L4.1@4467.92,2001.92 v1(4500,2034) 4508,2042 v1(4508,2081)
  Bottom Layer - L10 w25: v1(5954,2165) 5900,2111 5900,1809 6113,1596 6113,1355 6223,1245 6223,944 6289,878 6289,788 6251,750 R131.1@6251,569.71
  Bottom Layer - L10 w31.5: v1@5954,2162.44 C171.1@5954,2187.44
  Bottom Layer - L10 w37.5: L2.1@4467.92,1932.5 L4.1@4467.92,2001.92
  other v1: 3969.5,2062.35 5954,2190 4467.92,2240 3969.5,2278.89
VIO_3P3V_LMK_PLL: C102.1 C104.1 C107.1 C108.1 C109.1 C164.1 C165.1 C206.1 C207.1 C208.1 C209.1 L3.1 L5.1 L10.2 U6.10 U6.33 U6.39 U6.42 U6.47 | length 669.2
  Top Layer L1 w9: U6.47@4089.61,2320.23 v1(4089.61,2355.31) ; U6.42@4188.03,2320.23 v1(4188.03,2355.31) ; v1(4247.09,1938.69) U6.10@4247.09,1973.77 ; U6.39@4247.09,2320.23 v1(4247.09,2355.31) ; U6.33@4365.2,2320.23 v1(4365.2,2355.31)
  Top Layer L1 w31.5: L10.2@6026,2165.99 v1(6026,2317.5)
  Bottom Layer - L10 w18: C108.1@4047.92,2344.32 4055.79,2336.44 C209.1@4089.61,2336.45 v1(4089.61,2355.31) ; L5.1@4128.98,2459.5 C107.1@4179.92,2459.5 v1(4179.92,2440.63) ; C208.1@4188.03,2336.45 v1(4188.03,2355.31) ; L3.1@4201.96,2396.5 4209.05,2403.59 v1(4209.05,2447.5) C104.1@4209.05,2466.37 ; C109.1@4211.72,1957.55 C102.1@4247.09,1957.55 v1(4247.09,1938.69) ; C207.1@4247.09,2336.45 v1(4247.09,2355.31) ; C206.1@4365.2,2336.45 v1(4365.2,2355.31)
  Bottom Layer - L10 w31.5: v1(6026,2292.5) v1(6026,2317.5)
VIO_3P3V_LMX: C144.1 C152.1 C216.2 C217.2 C258.2 C259.2 C260.2 L1.1 L6.2 L27.1 L28.1 L29.1 L30.1 L31.1 L32.1 L33.1 L34.1 R130.1 R146.1 R151.1 R156.2 R157.2 R163.2 R164.2 U17.8 | length 3776.2
  Top Layer L1 w18: v1(4377,2642) 4377,2569.78 4401.91,2544.87 C259.2@4410.91,2544.87 v1(4410.91,2519) ; C258.2@4762.84,1544.09 v1(4762.84,1603.5) ; v1(5435.08,1490) 5446.92,1490 L30.1@5453.92,1483 ; L29.1@5492.55,1483 5499.55,1490 v1(5511.39,1490)
  Top Layer L1 w31.5: L6.2@6914,1876.5 6962.94,1876.5 v1(6976.44,1890)
  Bottom Layer - L10 w18: C260.2@4245.69,2537.87 4279.3,2537.87 ; R157.2@4279.3,2519 4279.3,2537.87 ; R156.2@4392.04,2519 v1(4410.91,2519) ; v1(4954.69,1790) 4954.69,2233.31 4546,2642 4337,2642 4279.3,2584.3 4279.3,2537.87
  Bottom Layer - L10 w25: v1(6168.2,1540) v1(6168.2,1390) 6315,1243.2 6315,944 6339,920 6339,757 6300,718 R130.1@6300,550.02
  Bottom Layer - L10 w31.5: v1(6074.87,1790) v1(6124.87,1790) 6124.87,1812.87 6154,1842 6866,1842 v1(6914,1890) v1(6976.44,1890)
  other v1: 5995.69,1415 5524.31,1432.5 4762.84,1572.81 5239.44,1615 5051.36,1620.81 5197.69,1620.82 5742,1692.98 5781.52,1733.13 5051.36,1736.19 5084.68,1790 5753.92,1790 5778.92,1790 6099.87,1790 4954.69,1842 5331.35,2019.09 5521.12,2019.09
VIO_3P75_U19: "5401 PD.2" C265.1 C267.2 C269.2 C271.1 C273.1 C274.1 C275.1 C280.1 C281.1 L43.2 R188.2 R240.1 R241.2 U19.1 U19.10 VIO_3P75_U19.1 | length 660.7
  Top Layer L1 w19.68: C265.1@3250.87,1237.02 C265.1@3273.64,1237.02 ; C271.1@3250.87,1423.29 C271.1@3273.64,1423.29
  Top Layer L1 w21.46: C265.1@3250.87,1237.02 v2(3250.87,1258.4) 3250.87,1280.91 3241.95,1289.83 v2(3241.95,1315.42) v2(3241.95,1344.89) 3241.95,1370.48 3250.87,1379.4 v2(3250.87,1401.91) C271.1@3250.87,1423.29
  Top Layer L1 w24: C281.1@3021.57,1006.97 v3(3050.81,1006.97) L43.2@3080.04,1006.97
  Top Layer L1 w37.4: L43.2@3082.01,1006.96 VIO_3P75_U19.1@3082.01,1079
  Bottom Layer - L10 w9.84: v2(3241.95,1315.42) 3246.91,1310.74 3246.91,1262.37 v2(3250.87,1258.4) ; v2(3241.95,1344.89) 3246.91,1349.57 U19.10@3246.91,1375.43 3246.91,1397.94 v2(3250.87,1401.91)
  Bottom Layer - L10 w19.68: C267.2@3250.87,1237.02 C267.2@3273.64,1237.02 ; C269.2@3250.87,1423.29 C269.2@3273.64,1423.29 ; R188.2@3303.3,1122.68 v2(3325.75,1122.68)
  Bottom Layer - L10 w21.46: v2(3241.95,1315.42) v2(3241.95,1344.89) ; C267.2@3250.87,1237.02 v2(3250.87,1258.4) ; v2(3250.87,1401.91) C269.2@3250.87,1423.29
  Bottom Layer - L10 w24: C280.1@3021.57,1006.97 v3(3050.81,1006.97)
  other v2: 3101.86,1224.63 3264.87,1236.94 3264.87,1423.38 3101.86,1435.69
  other v3: 3299.34,1025
VIO_3P75_U23: "6401 PD.2" C3.1 C4.1 C5.1 C100.1 C297.1 C298.1 C302.1 C304.2 C306.2 C308.1 L45.2 R183.1 U23.8 U23.13 U25.5 VIO_3P75_U23.1 | length 738.9
  Top Layer L1 w15.75: v1(3714.83,1043) v1(3714.83,1084.41)
  Top Layer L1 w19.68: v2(3574.41,1306.63) 3574.41,1287.21 C4.1@3575.57,1286.06 3575.57,1275.37 v2(3596.38,1254.56) ; v2(3574.41,1353.68) 3574.41,1373.1 C5.1@3575.57,1374.26 3575.57,1384.95 v2(3596.38,1405.76)
  Top Layer L1 w21.46: v2(3574.41,1306.63) v2(3574.41,1353.68) ; v2(3596.38,1254.56) 3596.38,1233.09 C302.1@3619.15,1233.09 ; v2(3596.38,1405.76) 3596.38,1427.22 C308.1@3619.15,1427.22
  Top Layer L1 w24: L45.2@3244.01,880.98 3250,874.99 v3(3250,846.49) C298.1@3250,818.24
  Top Layer L1 w31.5: VIO_3P75_U23.1@3173,880.98 L45.2@3244.01,880.98
  Bottom Layer - L10 w9.84: v2(3574.41,1306.63) 3574.41,1300.55 3585.41,1289.55 U23.13@3585.41,1275.04 3585.41,1265.53 v2(3596.38,1254.56) ; v2(3574.41,1353.68) 3574.41,1359.76 3585.41,1370.76 U23.8@3585.41,1385.28 3585.41,1394.79 v2(3596.38,1405.76)
  Bottom Layer - L10 w16: v1(3784.51,718.32) R183.1@3801.78,718.32
  Bottom Layer - L10 w21.46: v2(3574.41,1306.63) v2(3574.41,1353.68) ; v2@3596.38,1254.47 3596.38,1233.09 C304.2@3619.15,1233.09 ; v2@3596.38,1405.67 3596.38,1427.22 C306.2@3619.15,1427.22
  Bottom Layer - L10 w24: C297.1@3250,818.24 v3(3250,846.49)
  other v2: 3668.88,910 3610.38,1233.09 3610.38,1427.14
VIO_4P05V: C154.2 C156.2 C157.2 L7.1 L8.2 L35.1 L36.1 L40.1 L53.1 R72.1 | length 2010.7
  Top Layer L1 w18: R72.1@7838.88,995 C154.2@7838.88,1044
  Top Layer L1 w24: v3(867.88,846.31) v3(900.07,846.31) ; v3(2324.5,727.41) v3(2324.5,759.59) ; v3(3013.5,727.41) v3(3013.5,759.59) ; v3(3145.13,670) v3(3177.31,670)
  Bottom Layer - L10 w18: v1(7838.88,990) 8040.85,1191.97 v1(8040.85,1646.25)
  Bottom Layer - L10 w31.5: v1(5005,1340) v1(5030,1340) v1(5055,1340) v1(5080,1340) 5967,1340 v1(6042,1415) v1(6067,1415)
  other v1: 8040.85,1671.25
VIO_5: C389.1 C390.1 L50.2 U44.1 U44.3 | length 348.6
  Top Layer L1 w23.62: C390.1@396.13,2099 U44.1@396.13,2153.6 ; U44.3@396.13,2228.4 v3(396.13,2252.71)
  Top Layer L1 w24: C390.1@396.13,2099 v3(424.38,2099)
  Top Layer L1 w31.5: L50.2@396.13,2039.5 C390.1@396.13,2099
  Bottom Layer - L10 w24: v3(396.13,2252.71) C389.1@396.13,2099 v3(424.38,2099)
VIO_5V: C386.2 C387.2 C388.2 C394.2 C397.2 C400.2 C403.2 FL1.1 FL2.1 FL3.1 L50.1 R243.1 R245.2 U43.9 | length 2397.8
  Top Layer L1 w19.68: R243.1@1759.32,1056.68 v3(1781.67,1056.68)
  Top Layer L1 w24: v3(396,1944.32) v3(396,1976.5)
  Top Layer L1 w25: v3(976,644.11) C394.2@976,684.17 v3(976,724.23) FL1.1@976,756.42 ; v3(1126,644.11) C400.2@1126,684.17 v3(1126,724.23) FL2.1@1126,756.42 ; v3(1276,644.11) C397.2@1276,684.17 v3(1276,724.23) FL3.1@1276,756.42 ; C387.2@1428.94,929.53 v3(1428.94,963.68) ; C387.2@1459.06,929.53 v3(1459.06,963.68)
  Signals - L8 w25: v3(396,1976.5) 396,1799 497,1698 1178,1698 1289,1587 1289,1161 1428.94,1021.06 v3(1428.94,963.68) v3(1459.06,963.68)
  Bottom Layer - L10 w25: C388.2@1428.94,929.53 v3(1428.94,963.68) ; C388.2@1459.06,929.53 v3(1459.06,963.68)
VIO_5V_DRV: C346.1 C347.2 C349.2 C401.1 C402.1 FL2.3 K7.7 K8.7 Q2.1 Q2.4 Q3.1 Q3.4 Q4.1 Q4.4 U26.14 U27.9 U29.9 VIO_5V_DRV.1 | length 4298.2
  Top Layer L1 w12: Q3.1@1757,1876.39 v2(1757,1893.12) ; v2(1807,1819.65) Q3.4@1807,1836.39 ; Q4.1@1901,1876.39 v2(1901,1893.12) ; v2(1951,1819.65) Q4.4@1951,1836.39 ; Q2.1@2045,1876.39 v2(2045,1893.12) ; v2(2095,1819.65) Q2.4@2095,1836.39
  Top Layer L1 w19.68: v2(1104.77,1746.84) C347.2@1127.31,1746.84 ; v2(2280.77,1746.84) C349.2@2303.31,1746.84
  Top Layer L1 w31.5: FL2.3@1126,933.58 C402.1@1126,995 VIO_5V_DRV.1@1126,1057
  Signals - L8 w25: VIO_5V_DRV.1@1126,1057 v3(1126,965.77) 1192.77,899 1319,899 1415,803 v3(1415,640)
  Bottom Layer - L10 w17.72: v2(1104.77,1746.84) U27.9@1104.77,1766.43 ; v2(1545.64,1766.23) U26.14@1565.23,1766.23 ; v2(2280.77,1746.84) U29.9@2280.77,1766.43
  Bottom Layer - L10 w19.68: C346.1@1519.06,1766.23 v2(1545.64,1766.23)
  Bottom Layer - L10 w25: v3(1415,674.49) v3(1415,640) 1477,578 2108,578 2460,226 3614,226 ; K7.7@3614,76 3614,226 ; K8.7@4239,76 4089,226 3614,226
  Bottom Layer - L10 w31.5: v3(1126,965.77) C401.1@1126,995 VIO_5V_DRV.1@1126,1057
VIO_5V_LMC: C331.2 C332.2 C333.2 C334.2 C335.2 C336.2 C337.2 C338.2 C339.2 C340.2 C355.1 C360.1 C361.1 C362.1 C363.1 C364.1 C365.1 C366.1 C367.1 C368.1 C369.1 C395.1 C396.1 FL1.3 R213.1 R214.1 R215.1 R216.1 R217.1 R218.1 R219.1 R220.1 R221.1 R222.1 R224.2 R225.2 R226.2 R227.2 R228.2 R234.2 R235.2 R236.2 R237.2 R238.2 U30.4 U30.8 U31.4 U31.8 U32.4 U32.8 U33.4 U33.8 U34.4 U34.8 U35.4 U35.8 U36.4 U36.8 U37.4 U37.8 U38.4 U38.8 U39.4 U39.8 U41.5 VIO_5V_LMC.1 | length 3098.4
  Top Layer L1 w15.75: R234.2@675.11,1995 681.02,1989.09 v2(681.02,1938.48) ; R236.2@675.11,2295 681.02,2289.09 v2(681.02,2238.48) ; R237.2@1139.11,2295 1145.02,2289.09 v2(1145.02,2238.48) ; R238.2@1139.11,2595 1145.02,2589.09 v2(1145.02,2538.48) ; R225.2@1516.11,2259 1522.02,2253.09 v2(1522.02,2238.48) ; R226.2@1516.11,2559 1522.02,2553.09 v2(1522.02,2538.48) ; R227.2@1987.11,2259 1993.02,2253.09 v2(1993.02,2238.48) ; R235.2@1987.11,2595 1993.02,2589.09 v2(1993.02,2538.48) ; R224.2@2364.11,2559 2370.02,2553.09 v2(2370.02,2538.48) ; R228.2@2365.11,2259 2371.02,2253.09 v2(2371.02,2238.48)
  Top Layer L1 w19.68: v2(1698.18,2366.4) C355.1@1698.18,2390.32
  Top Layer L1 w31.5: FL1.3@976,933.58 v3(976,965.77) C396.1@976,995 VIO_5V_LMC.1@976,1057
  Bottom Layer - L10 w15.75: v2(604.25,1773.13) U30.8@604.25,1817.32 ; v2(604.25,2073.13) U31.8@604.25,2117.32 ; v2(681.02,1938.48) U30.4@681.02,1982.68 ; v2(681.02,2238.48) U31.4@681.02,2282.68 ; v2(1068.25,2073.13) U34.8@1068.25,2117.32 ; v2(1068.25,2373.13) U36.8@1068.25,2417.32 ; v2(1145.02,2238.48) U34.4@1145.02,2282.68 ; v2(1145.02,2538.48) U36.4@1145.02,2582.68 ; v2(1445.25,2073.13) U35.8@1445.25,2117.32 ; v2(1445.25,2373.13) U37.8@1445.25,2417.32 ; v2(1522.02,2238.48) U35.4@1522.02,2282.68 ; v2(1522.02,2538.48) U37.4@1522.02,2582.68 ; v2(1916.25,2073.13) U38.8@1916.25,2117.32 ; v2(1916.25,2373.13) U32.8@1916.25,2417.32 ; v2(1993.02,2238.48) U38.4@1993.02,2282.68 ; v2(1993.02,2538.48) U32.4@1993.02,2582.68 ; v2(2293.25,2373.13) U33.8@2293.25,2417.32 ; v2(2294.25,2073.13) U39.8@2294.25,2117.32 ; v2(2370.02,2538.48) U33.4@2370.02,2582.68 ; v2(2371.02,2238.48) U39.4@2371.02,2282.68
  Bottom Layer - L10 w17.72: v2(584.66,1831.12) 604.25,1831.12 U30.8@604.25,1817.32 ; v2(584.66,2131.12) 604.25,2131.12 U31.8@604.25,2117.32 ; v2(1048.66,2131.12) 1068.25,2131.12 U34.8@1068.25,2117.32 ; v2(1048.66,2431.12) 1068.25,2431.12 U36.8@1068.25,2417.32 ; v2(1425.66,2131.12) 1445.25,2131.12 U35.8@1445.25,2117.32 ; v2(1425.66,2431.12) 1445.25,2431.12 U37.8@1445.25,2417.32 ; v2(1896.66,2131.12) 1916.25,2131.12 U38.8@1916.25,2117.32 ; v2(1896.66,2431.12) 1916.25,2431.12 U32.8@1916.25,2417.32 ; v2(2273.66,2431.12) 2293.25,2431.12 U33.8@2293.25,2417.32 ; v2(2274.66,2131.12) 2294.25,2131.12 U39.8@2294.25,2117.32
  Bottom Layer - L10 w19.68: v2(558,1857.77) C331.2@558,1880.31 ; v2(558,2157.77) C332.2@558,2180.31 ; v2(1022,2157.77) C335.2@1022,2180.31 ; v2(1022,2457.77) C337.2@1022,2480.31 ; v2(1399,2157.77) C336.2@1399,2180.31 ; v2(1399,2457.77) C338.2@1399,2480.31 ; v2(1870,2157.77) C339.2@1870,2180.31 ; v2(1870,2457.77) C333.2@1870,2480.31 ; v2(2247,2157.77) C340.2@2247,2180.31 ; v2(2247,2457.77) C334.2@2247,2480.31
  Bottom Layer - L10 w21.46: C360.1@495,1857.77 v2(558,1857.77) v2(584.66,1831.12) ; C361.1@495,2157.77 v2(558,2157.77) v2(584.66,2131.12) ; C364.1@959,2157.77 v2(1022,2157.77) v2(1048.66,2131.12) ; C366.1@959,2457.77 v2(1022,2457.77) v2(1048.66,2431.12) ; C365.1@1336,2157.77 v2(1399,2157.77) v2(1425.66,2131.12) ; C367.1@1336,2457.77 v2(1399,2457.77) v2(1425.66,2431.12) ; C368.1@1807,2157.77 v2(1870,2157.77) v2(1896.66,2131.12) ; C362.1@1807,2457.77 v2(1870,2457.77) v2(1896.66,2431.12) ; C369.1@2184,2157.77 v2(2247,2157.77) v2@2273.66,2131.12 ; C363.1@2184,2457.77 v2(2247,2457.77) v2(2273.66,2431.12)
  Bottom Layer - L10 w31.5: v3(976,965.77) C395.1@976,995 VIO_5V_LMC.1@976,1057
  other v2: 495,1824.12 495,2124.12 959,2124.12 1336,2124.12 1807,2124.12 2184,2124.12 959,2424.12 1336,2424.12 1807,2424.12 2184,2424.12
VIO_5V_LMH: "OFFSET ADJ.1" C353.1 C391.1 C392.1 C413.1 L51.2 U40.5 VIO_5V_LMH.1 | length 232.7
  Top Layer L1 w24: v3(98.75,2286) C392.1@127,2286
  Top Layer L1 w31.5: L51.2@127,2226.43 C392.1@127,2286
  Top Layer L1 w37.4: VIO_5V_LMH.1@55.99,2226.43 L51.2@127,2226.43
  Bottom Layer - L10 w15.75: U40.5@253.32,1648.4 v2(253.32,1694)
  Bottom Layer - L10 w24: v3(98.75,2286) C391.1@127,2286
  other v2: 252.33,1648.4 34.15,1672.21 75.68,1672.21
VIO_5V_LOGIC: C398.1 C399.1 FL3.3 K1.3 K1.8 K2.3 K2.8 K3.3 K3.8 K4.3 K4.8 K5.3 K5.8 VIO_5V_LOGIC.1 | length 1620.4
  Top Layer L1 w31.5: FL3.3@1276,933.58 C399.1@1276,995 VIO_5V_LOGIC.1@1276,1057
  Signals - L8 w25: K1.3@415,1430.16 515,1330.16 K1.8@515,1230.16 605.16,1140 1193,1140 VIO_5V_LOGIC.1@1276,1057 ; K2.8@985,1430.16 1085,1330.16 K2.3@1085,1230.16 1085,1140
  Bottom Layer - L10 w31.5: v3(1276,965.77) C398.1@1276,995 VIO_5V_LOGIC.1@1276,1057
VIO_-1P25_U19: C264.2 C266.1 C268.1 C270.2 C273.2 C274.2 C275.2 C289.1 C290.1 L44.2 R189.1 U19.3 U19.8 VIO_-1P25_U19.1 | length 659.7
  Top Layer L1 w19.68: C264.2@3180.8,1237.02 C264.2@3203.57,1237.02 ; C270.2@3180.8,1423.29 C270.2@3203.57,1423.29
  Top Layer L1 w21.46: C264.2@3203.57,1237.02 v2(3203.57,1258.4) 3203.57,1280.91 C273.2@3207.54,1284.88 3212.49,1289.83 v2(3212.49,1315.42) v2(3212.49,1344.89) 3212.49,1370.48 C274.2@3207.54,1375.43 3203.57,1379.4 v2(3203.57,1401.91) C270.2@3203.57,1423.29
  Top Layer L1 w24: L44.2@2475.01,946.02 v3(2504.24,946.02) C289.1@2533.47,946.02
  Top Layer L1 w31.5: VIO_-1P25_U19.1@2404,946.02 L44.2@2475.01,946.02
  Bottom Layer - L10 w9.84: v2(3203.57,1258.4) 3207.54,1262.37 U19.3@3207.54,1284.88 3207.54,1310.74 v2(3212.49,1315.42) ; v2(3203.57,1401.91) 3207.54,1397.94 U19.8@3207.54,1375.43 3207.54,1349.57 v2(3212.49,1344.89)
  Bottom Layer - L10 w19.68: v2(3128.69,1122.68) R189.1@3151.14,1122.68 ; C266.1@3180.8,1237.02 C266.1@3203.57,1237.02 ; C268.1@3180.8,1423.29 C268.1@3203.57,1423.29
  Bottom Layer - L10 w21.46: C266.1@3203.57,1237.02 v2(3203.57,1258.4) ; v2(3203.57,1401.91) C268.1@3203.57,1423.29 ; v2(3212.49,1315.42) v2(3212.49,1344.89)
  Bottom Layer - L10 w24: v3(2504.24,946.02) C290.1@2533.47,946.02
  other v2: 3189.57,1236.94 3189.57,1423.38
  other v3: 3196.98,1025
VIO_-1P25_U23: C3.2 C4.2 C5.2 C299.1 C300.1 C301.2 C303.1 C305.1 C307.2 L46.2 R182.1 U23.5 U23.16 VIO_-1P25_U23.1 | length 697.5
  Top Layer L1 w19.68: v2(3515.39,1254.56) 3536.2,1275.37 C4.2@3536.2,1286.06 3537.35,1287.21 v2(3537.35,1306.63) ; v2(3515.39,1405.76) 3536.2,1384.95 C5.2@3536.2,1374.26 3537.35,1373.1 v2(3537.35,1353.68)
  Top Layer L1 w21.46: C301.2@3492.62,1233.1 3515.39,1233.09 v2(3515.39,1254.56) ; C307.2@3492.62,1427.22 3515.39,1427.22 v2(3515.39,1405.76) ; v2(3537.35,1306.63) v2(3537.35,1353.68)
  Top Layer L1 w24: L46.2@2475.01,745.98 2481,739.99 v3(2481,711.49) C300.1@2481,683.24
  Top Layer L1 w31.5: VIO_-1P25_U23.1@2404,745.98 L46.2@2475.01,745.98
  Bottom Layer - L10 w9.84: v2(3515.39,1254.56) 3526.35,1265.53 U23.16@3526.35,1275.04 3526.35,1289.55 3537.35,1300.55 v2(3537.35,1306.63) ; v2(3515.39,1405.76) 3526.35,1394.79 U23.5@3526.35,1385.28 3526.35,1370.76 3537.35,1359.76 v2(3537.35,1353.68)
  Bottom Layer - L10 w16: v1(3784.51,835.69) R182.1@3801.78,835.68
  Bottom Layer - L10 w21.46: C303.1@3492.62,1233.09 3515.39,1233.09 v2@3515.39,1254.47 ; C305.1@3492.62,1427.22 3515.39,1427.22 v2@3515.39,1405.67 ; v2(3537.35,1306.63) v2(3537.35,1353.68)
  Bottom Layer - L10 w24: C299.1@2481,683.24 v3(2481,711.49)
  other v2: 3517.12,910 3501.39,1233.01 3501.39,1427.22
